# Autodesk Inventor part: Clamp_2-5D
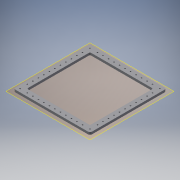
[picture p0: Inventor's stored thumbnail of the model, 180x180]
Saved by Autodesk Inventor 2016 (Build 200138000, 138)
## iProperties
Created: 2015-11
Part Number: Clamp_2-5D
Material: Generic
Document SubType Name: Modeling
Designer: John
Density: 1 g/cm^3
Appearance: Default
Author: John
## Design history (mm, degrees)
workplane "Work Plane1"
sketch "Sketch1"
  geometry: L1 (82.3, -85.475)-(-82.3, -85.475) reference; L2 (-85.475, -82.3)-(-85.475, 82.3) reference; L3 (-82.3, 85.475)-(82.3, 85.475) reference; L4 (85.475, 82.3)-(85.475, -82.3) reference; L5 (-98.475, 103.475)-(98.475, 103.475) reference; L6 (-103.475, -98.475)-(-103.475, 98.475) reference; L7 (98.475, -103.475)-(-98.475, -103.475) reference; L8 (103.475, 98.475)-(103.475, -98.475) reference; C1 r 1.75 at (95, 44.824) reference; C2 r 1.75 at (95, 59.766) reference; C3 r 1.75 at (95, 29.886) reference; C4 r 1.75 at (95, -0.002) reference; C5 r 1.75 at (95, -29.886) reference; C6 r 1.75 at (95, -59.77) reference; C7 r 1.75 at (95, -74.708) reference; C8 r 1.75 at (94.65, 94.65) reference; C9 r 1.75 at (95, 74.708) reference; C10 r 1.75 at (95, -44.828) reference; C11 r 1.75 at (95, -14.944) reference; C12 r 1.75 at (95, 14.944) reference; C13 r 1.75 at (-44.824, 95) reference; C14 r 1.75 at (-59.766, 95) reference; C15 r 1.75 at (-29.886, 95) reference; C16 r 1.75 at (0.002, 95) reference; C17 r 1.75 at (29.886, 95) reference; C18 r 1.75 at (59.77, 95) reference; C19 r 1.75 at (74.708, 95) reference; C20 r 1.75 at (-74.708, 95) reference; C21 r 1.75 at (44.828, 95) reference; C22 r 1.75 at (14.944, 95) reference; C23 r 1.75 at (-14.944, 95) reference; C24 r 1.75 at (14.944, -95) reference; C25 r 1.75 at (-14.944, -95) reference; C26 r 1.75 at (-44.828, -95) reference; C27 r 1.75 at (74.708, -95) reference; C28 r 1.75 at (94.65, -94.65) reference; C29 r 1.75 at (-74.708, -95) reference; C30 r 1.75 at (-59.77, -95) reference; C31 r 1.75 at (-29.886, -95) reference; C32 r 1.75 at (-0.002, -95) reference; C33 r 1.75 at (29.886, -95) reference; C34 r 1.75 at (59.766, -95) reference; C35 r 1.75 at (44.824, -95) reference; C36 r 1.75 at (-95, -44.824) reference; C37 r 1.75 at (-95, -59.766) reference; C38 r 1.75 at (-95, -29.886) reference; C39 r 1.75 at (-95, 0.002) reference; C40 r 1.75 at (-95, 29.886) reference; C41 r 1.75 at (-95, 59.77) reference; C42 r 1.75 at (-95, 74.708) reference; C43 r 1.75 at (-94.65, -94.65) reference; C44 r 1.75 at (-94.65, 94.65) reference; C45 r 1.75 at (-95, -74.708) reference; C46 r 1.75 at (-95, 44.828) reference; C47 r 1.75 at (-95, 14.944) reference; C48 r 1.75 at (-95, -14.944) reference; A1 r 3.175 centre (-82.3, -82.3) between (-85.475, -82.3) and (-82.3, -85.475) reference; A2 r 3.175 centre (-82.3, 82.3) between (-82.3, 85.475) and (-85.475, 82.3) reference; A3 r 3.175 centre (82.3, 82.3) between (85.475, 82.3) and (82.3, 85.475) reference; A4 r 3.175 centre (82.3, -82.3) between (82.3, -85.475) and (85.475, -82.3) reference; A5 r 5 centre (98.475, 98.475) between (103.475, 98.475) and (98.475, 103.475) reference; A6 r 5 centre (-98.475, 98.475) between (-98.475, 103.475) and (-103.475, 98.475) reference; A7 r 5 centre (-98.475, -98.475) between (-103.475, -98.475) and (-98.475, -103.475) reference; A8 r 5 centre (98.475, -98.475) between (98.475, -103.475) and (103.475, -98.475) reference; 1 further point
extrude "Extrusion1" new body sketch "Sketch1" distance "d0" = 6.35; taper "d1" = 0 deg
body "Solid1"
node "Reference1"
